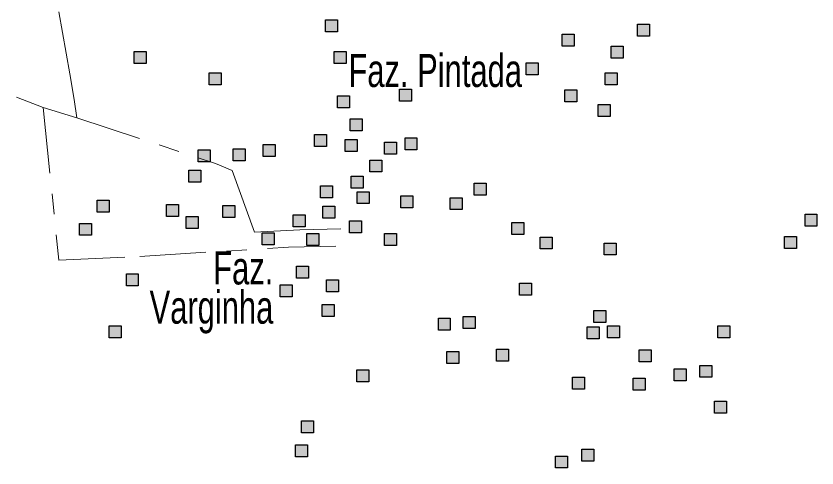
# Model space of a CAD drawing. Extents: x 445.4 to 500, y 8728.7 to 8784.
# Drawn here: x 445.43 to 449.31, y 8748.527 to 8750.716 of the extents above; entities that cross this region are included whole.
import ezdxf
from ezdxf.enums import TextEntityAlignment as Align

# ---------------------------------------------------------------- set-up
doc = ezdxf.new("R2010")
doc.units = 0
doc.header["$LTSCALE"] = 0.064
doc.linetypes.add('DOT_DASHED', pattern=[7.7, 5, -1.2, 0.3, -1.2])
doc.layers.add('2', color=7, linetype='Continuous', lineweight=25)
doc.layers.add('22', color=7, linetype='DOT_DASHED', lineweight=13)
doc.layers.add('61', color=7, linetype='Continuous')

msp = doc.modelspace()

# ---------------------------------------------------------------- hatches: boundary and pattern name
at = {"layer": '2'}
for points in [[(446.9291, 8750.6983), (446.9871, 8750.6983), (446.9871, 8750.6403), (446.9291, 8750.6403)], [(448.4407, 8750.6776), (448.4987, 8750.6776), (448.4987, 8750.6196), (448.4407, 8750.6196)], [(448.0762, 8750.6279), (448.1342, 8750.6279), (448.1342, 8750.5699), (448.0762, 8750.5699)], [(448.3123, 8750.5699), (448.3703, 8750.5699), (448.3703, 8750.5119), (448.3123, 8750.5119)], [(446.0014, 8750.545), (446.0594, 8750.545), (446.0594, 8750.487), (446.0014, 8750.487)], [(446.9705, 8750.545), (447.0285, 8750.545), (447.0285, 8750.487), (446.9705, 8750.487)], [(447.9019, 8750.49), (447.9599, 8750.49), (447.9599, 8750.432), (447.9019, 8750.432)], [(446.3659, 8750.4414), (446.4239, 8750.4414), (446.4239, 8750.3834), (446.3659, 8750.3834)], [(448.2833, 8750.4414), (448.3413, 8750.4414), (448.3413, 8750.3834), (448.2833, 8750.3834)], [(446.9871, 8750.3295), (447.0451, 8750.3295), (447.0451, 8750.2715), (446.9871, 8750.2715)], [(447.2873, 8750.3627), (447.3453, 8750.3627), (447.3453, 8750.3047), (447.2873, 8750.3047)], [(448.0886, 8750.3585), (448.1466, 8750.3585), (448.1466, 8750.3005), (448.0886, 8750.3005)], [(448.2502, 8750.2881), (448.3082, 8750.2881), (448.3082, 8750.2301), (448.2502, 8750.2301)], [(447.0492, 8750.2177), (447.1072, 8750.2177), (447.1072, 8750.1597), (447.0492, 8750.1597)], [(446.8752, 8750.1431), (446.9332, 8750.1431), (446.9332, 8750.0851), (446.8752, 8750.0851)], [(446.6268, 8750.0933), (446.6848, 8750.0933), (446.6848, 8750.0353), (446.6268, 8750.0353)], [(447.0243, 8750.1182), (447.0823, 8750.1182), (447.0823, 8750.0602), (447.0243, 8750.0602)], [(447.2148, 8750.1058), (447.2728, 8750.1058), (447.2728, 8750.0478), (447.2148, 8750.0478)], [(447.3142, 8750.1265), (447.3722, 8750.1265), (447.3722, 8750.0685), (447.3142, 8750.0685)], [(446.312, 8750.0685), (446.37, 8750.0685), (446.37, 8750.0105), (446.312, 8750.0105)], [(446.4818, 8750.0726), (446.5398, 8750.0726), (446.5398, 8750.0146), (446.4818, 8750.0146)], [(447.1444, 8750.0188), (447.2024, 8750.0188), (447.2024, 8749.9608), (447.1444, 8749.9608)], [(446.2665, 8749.969), (446.3245, 8749.969), (446.3245, 8749.911), (446.2665, 8749.911)], [(447.0533, 8749.94), (447.1113, 8749.94), (447.1113, 8749.882), (447.0533, 8749.882)], [(447.6497, 8749.9069), (447.7077, 8749.9069), (447.7077, 8749.8489), (447.6497, 8749.8489)], [(446.9042, 8749.8944), (446.9622, 8749.8944), (446.9622, 8749.8364), (446.9042, 8749.8364)], [(447.0823, 8749.8654), (447.1403, 8749.8654), (447.1403, 8749.8074), (447.0823, 8749.8074)], [(445.8233, 8749.824), (445.8813, 8749.824), (445.8813, 8749.766), (445.8233, 8749.766)], [(447.2935, 8749.8447), (447.3515, 8749.8447), (447.3515, 8749.7867), (447.2935, 8749.7867)], [(447.5337, 8749.8364), (447.5917, 8749.8364), (447.5917, 8749.7784), (447.5337, 8749.7784)], [(446.1588, 8749.8033), (446.2168, 8749.8033), (446.2168, 8749.7453), (446.1588, 8749.7453)], [(446.4321, 8749.7991), (446.4901, 8749.7991), (446.4901, 8749.7411), (446.4321, 8749.7411)], [(446.9166, 8749.795), (446.9746, 8749.795), (446.9746, 8749.737), (446.9166, 8749.737)], [(446.254, 8749.7453), (446.312, 8749.7453), (446.312, 8749.6873), (446.254, 8749.6873)], [(446.7717, 8749.7535), (446.8297, 8749.7535), (446.8297, 8749.6955), (446.7717, 8749.6955)], [(449.2521, 8749.7568), (449.3101, 8749.7568), (449.3101, 8749.6988), (449.2521, 8749.6988)], [(445.7364, 8749.7121), (445.7944, 8749.7121), (445.7944, 8749.6541), (445.7364, 8749.6541)], [(447.045, 8749.7245), (447.103, 8749.7245), (447.103, 8749.6665), (447.045, 8749.6665)], [(447.8319, 8749.7163), (447.8899, 8749.7163), (447.8899, 8749.6583), (447.8319, 8749.6583)], [(446.6226, 8749.6665), (446.6806, 8749.6665), (446.6806, 8749.6085), (446.6226, 8749.6085)], [(446.838, 8749.6624), (446.896, 8749.6624), (446.896, 8749.6044), (446.838, 8749.6044)], [(447.2148, 8749.6624), (447.2728, 8749.6624), (447.2728, 8749.6044), (447.2148, 8749.6044)], [(447.9685, 8749.6458), (448.0265, 8749.6458), (448.0265, 8749.5878), (447.9685, 8749.5878)], [(449.1527, 8749.649), (449.2107, 8749.649), (449.2107, 8749.591), (449.1527, 8749.591)], [(448.2791, 8749.6168), (448.3371, 8749.6168), (448.3371, 8749.5588), (448.2791, 8749.5588)], [(446.7883, 8749.5049), (446.8463, 8749.5049), (446.8463, 8749.4469), (446.7883, 8749.4469)], [(445.9641, 8749.4676), (446.0221, 8749.4676), (446.0221, 8749.4096), (445.9641, 8749.4096)], [(446.9332, 8749.4386), (446.9912, 8749.4386), (446.9912, 8749.3806), (446.9332, 8749.3806)], [(446.7096, 8749.4138), (446.7676, 8749.4138), (446.7676, 8749.3558), (446.7096, 8749.3558)], [(447.8692, 8749.422), (447.9272, 8749.422), (447.9272, 8749.364), (447.8692, 8749.364)], [(446.9125, 8749.3184), (446.9705, 8749.3184), (446.9705, 8749.2604), (446.9125, 8749.2604)], [(448.2294, 8749.2894), (448.2874, 8749.2894), (448.2874, 8749.2314), (448.2294, 8749.2314)], [(447.4757, 8749.2521), (447.5337, 8749.2521), (447.5337, 8749.1941), (447.4757, 8749.1941)], [(447.5958, 8749.2604), (447.6538, 8749.2604), (447.6538, 8749.2024), (447.5958, 8749.2024)], [(445.8813, 8749.2149), (445.9393, 8749.2149), (445.9393, 8749.1569), (445.8813, 8749.1569)], [(448.1963, 8749.2107), (448.2543, 8749.2107), (448.2543, 8749.1527), (448.1963, 8749.1527)], [(448.2957, 8749.2149), (448.3537, 8749.2149), (448.3537, 8749.1569), (448.2957, 8749.1569)], [(448.8299, 8749.2149), (448.8879, 8749.2149), (448.8879, 8749.1569), (448.8299, 8749.1569)], [(447.5171, 8749.0905), (447.5751, 8749.0905), (447.5751, 8749.0325), (447.5171, 8749.0325)], [(447.7573, 8749.103), (447.8153, 8749.103), (447.8153, 8749.045), (447.7573, 8749.045)], [(448.4489, 8749.0988), (448.5069, 8749.0988), (448.5069, 8749.0408), (448.4489, 8749.0408)], [(448.6187, 8749.0077), (448.6767, 8749.0077), (448.6767, 8748.9497), (448.6187, 8748.9497)], [(448.743, 8749.0242), (448.801, 8749.0242), (448.801, 8748.9662), (448.743, 8748.9662)], [(447.0803, 8749.0022), (447.1383, 8749.0022), (447.1383, 8748.9442), (447.0803, 8748.9442)], [(448.1259, 8748.9662), (448.1839, 8748.9662), (448.1839, 8748.9082), (448.1259, 8748.9082)], [(448.4199, 8748.9621), (448.4779, 8748.9621), (448.4779, 8748.9041), (448.4199, 8748.9041)], [(448.8134, 8748.8502), (448.8714, 8748.8502), (448.8714, 8748.7922), (448.8134, 8748.7922)], [(446.8131, 8748.7549), (446.8711, 8748.7549), (446.8711, 8748.6969), (446.8131, 8748.6969)], [(446.7841, 8748.6389), (446.8421, 8748.6389), (446.8421, 8748.5809), (446.7841, 8748.5809)], [(448.0431, 8748.585), (448.1011, 8748.585), (448.1011, 8748.527), (448.0431, 8748.527)], [(448.1715, 8748.6181), (448.2295, 8748.6181), (448.2295, 8748.5601), (448.1715, 8748.5601)]]:
    msp.add_hatch(color=256, dxfattribs=at).paths.add_polyline_path(points)

# ---------------------------------------------------------------- linework, layer by layer
for points in [[(446.9291, 8750.6983), (446.9871, 8750.6983), (446.9871, 8750.6403), (446.9291, 8750.6403)], [(448.4407, 8750.6776), (448.4987, 8750.6776), (448.4987, 8750.6196), (448.4407, 8750.6196)], [(448.0762, 8750.6279), (448.1342, 8750.6279), (448.1342, 8750.5699), (448.0762, 8750.5699)], [(448.3123, 8750.5699), (448.3703, 8750.5699), (448.3703, 8750.5119), (448.3123, 8750.5119)], [(446.0014, 8750.545), (446.0594, 8750.545), (446.0594, 8750.487), (446.0014, 8750.487)], [(446.9705, 8750.545), (447.0285, 8750.545), (447.0285, 8750.487), (446.9705, 8750.487)], [(447.9019, 8750.49), (447.9599, 8750.49), (447.9599, 8750.432), (447.9019, 8750.432)], [(446.3659, 8750.4414), (446.4239, 8750.4414), (446.4239, 8750.3834), (446.3659, 8750.3834)], [(448.2833, 8750.4414), (448.3413, 8750.4414), (448.3413, 8750.3834), (448.2833, 8750.3834)], [(446.9871, 8750.3295), (447.0451, 8750.3295), (447.0451, 8750.2715), (446.9871, 8750.2715)], [(447.2873, 8750.3627), (447.3453, 8750.3627), (447.3453, 8750.3047), (447.2873, 8750.3047)], [(448.0886, 8750.3585), (448.1466, 8750.3585), (448.1466, 8750.3005), (448.0886, 8750.3005)], [(448.2502, 8750.2881), (448.3082, 8750.2881), (448.3082, 8750.2301), (448.2502, 8750.2301)], [(447.0492, 8750.2177), (447.1072, 8750.2177), (447.1072, 8750.1597), (447.0492, 8750.1597)], [(446.8752, 8750.1431), (446.9332, 8750.1431), (446.9332, 8750.0851), (446.8752, 8750.0851)], [(446.6268, 8750.0933), (446.6848, 8750.0933), (446.6848, 8750.0353), (446.6268, 8750.0353)], [(447.0243, 8750.1182), (447.0823, 8750.1182), (447.0823, 8750.0602), (447.0243, 8750.0602)], [(447.2148, 8750.1058), (447.2728, 8750.1058), (447.2728, 8750.0478), (447.2148, 8750.0478)], [(447.3142, 8750.1265), (447.3722, 8750.1265), (447.3722, 8750.0685), (447.3142, 8750.0685)], [(446.312, 8750.0685), (446.37, 8750.0685), (446.37, 8750.0105), (446.312, 8750.0105)], [(446.4818, 8750.0726), (446.5398, 8750.0726), (446.5398, 8750.0146), (446.4818, 8750.0146)], [(447.1444, 8750.0188), (447.2024, 8750.0188), (447.2024, 8749.9608), (447.1444, 8749.9608)], [(446.2665, 8749.969), (446.3245, 8749.969), (446.3245, 8749.911), (446.2665, 8749.911)], [(447.0533, 8749.94), (447.1113, 8749.94), (447.1113, 8749.882), (447.0533, 8749.882)], [(447.6497, 8749.9069), (447.7077, 8749.9069), (447.7077, 8749.8489), (447.6497, 8749.8489)], [(446.9042, 8749.8944), (446.9622, 8749.8944), (446.9622, 8749.8364), (446.9042, 8749.8364)], [(447.0823, 8749.8654), (447.1403, 8749.8654), (447.1403, 8749.8074), (447.0823, 8749.8074)], [(445.8233, 8749.824), (445.8813, 8749.824), (445.8813, 8749.766), (445.8233, 8749.766)], [(447.2935, 8749.8447), (447.3515, 8749.8447), (447.3515, 8749.7867), (447.2935, 8749.7867)], [(447.5337, 8749.8364), (447.5917, 8749.8364), (447.5917, 8749.7784), (447.5337, 8749.7784)], [(446.1588, 8749.8033), (446.2168, 8749.8033), (446.2168, 8749.7453), (446.1588, 8749.7453)], [(446.4321, 8749.7991), (446.4901, 8749.7991), (446.4901, 8749.7411), (446.4321, 8749.7411)], [(446.9166, 8749.795), (446.9746, 8749.795), (446.9746, 8749.737), (446.9166, 8749.737)], [(446.254, 8749.7453), (446.312, 8749.7453), (446.312, 8749.6873), (446.254, 8749.6873)], [(446.7717, 8749.7535), (446.8297, 8749.7535), (446.8297, 8749.6955), (446.7717, 8749.6955)], [(449.2521, 8749.7568), (449.3101, 8749.7568), (449.3101, 8749.6988), (449.2521, 8749.6988)], [(445.7364, 8749.7121), (445.7944, 8749.7121), (445.7944, 8749.6541), (445.7364, 8749.6541)], [(447.045, 8749.7245), (447.103, 8749.7245), (447.103, 8749.6665), (447.045, 8749.6665)], [(447.8319, 8749.7163), (447.8899, 8749.7163), (447.8899, 8749.6583), (447.8319, 8749.6583)], [(446.6226, 8749.6665), (446.6806, 8749.6665), (446.6806, 8749.6085), (446.6226, 8749.6085)], [(446.838, 8749.6624), (446.896, 8749.6624), (446.896, 8749.6044), (446.838, 8749.6044)], [(447.2148, 8749.6624), (447.2728, 8749.6624), (447.2728, 8749.6044), (447.2148, 8749.6044)], [(447.9685, 8749.6458), (448.0265, 8749.6458), (448.0265, 8749.5878), (447.9685, 8749.5878)], [(449.1527, 8749.649), (449.2107, 8749.649), (449.2107, 8749.591), (449.1527, 8749.591)], [(448.2791, 8749.6168), (448.3371, 8749.6168), (448.3371, 8749.5588), (448.2791, 8749.5588)], [(446.7883, 8749.5049), (446.8463, 8749.5049), (446.8463, 8749.4469), (446.7883, 8749.4469)], [(445.9641, 8749.4676), (446.0221, 8749.4676), (446.0221, 8749.4096), (445.9641, 8749.4096)], [(446.9332, 8749.4386), (446.9912, 8749.4386), (446.9912, 8749.3806), (446.9332, 8749.3806)], [(446.7096, 8749.4138), (446.7676, 8749.4138), (446.7676, 8749.3558), (446.7096, 8749.3558)], [(447.8692, 8749.422), (447.9272, 8749.422), (447.9272, 8749.364), (447.8692, 8749.364)], [(446.9125, 8749.3184), (446.9705, 8749.3184), (446.9705, 8749.2604), (446.9125, 8749.2604)], [(448.2294, 8749.2894), (448.2874, 8749.2894), (448.2874, 8749.2314), (448.2294, 8749.2314)], [(447.4757, 8749.2521), (447.5337, 8749.2521), (447.5337, 8749.1941), (447.4757, 8749.1941)], [(447.5958, 8749.2604), (447.6538, 8749.2604), (447.6538, 8749.2024), (447.5958, 8749.2024)], [(445.8813, 8749.2149), (445.9393, 8749.2149), (445.9393, 8749.1569), (445.8813, 8749.1569)], [(448.1963, 8749.2107), (448.2543, 8749.2107), (448.2543, 8749.1527), (448.1963, 8749.1527)], [(448.2957, 8749.2149), (448.3537, 8749.2149), (448.3537, 8749.1569), (448.2957, 8749.1569)], [(448.8299, 8749.2149), (448.8879, 8749.2149), (448.8879, 8749.1569), (448.8299, 8749.1569)], [(447.5171, 8749.0905), (447.5751, 8749.0905), (447.5751, 8749.0325), (447.5171, 8749.0325)], [(447.7573, 8749.103), (447.8153, 8749.103), (447.8153, 8749.045), (447.7573, 8749.045)], [(448.4489, 8749.0988), (448.5069, 8749.0988), (448.5069, 8749.0408), (448.4489, 8749.0408)], [(448.6187, 8749.0077), (448.6767, 8749.0077), (448.6767, 8748.9497), (448.6187, 8748.9497)], [(448.743, 8749.0242), (448.801, 8749.0242), (448.801, 8748.9662), (448.743, 8748.9662)], [(447.0803, 8749.0022), (447.1383, 8749.0022), (447.1383, 8748.9442), (447.0803, 8748.9442)], [(448.1259, 8748.9662), (448.1839, 8748.9662), (448.1839, 8748.9082), (448.1259, 8748.9082)], [(448.4199, 8748.9621), (448.4779, 8748.9621), (448.4779, 8748.9041), (448.4199, 8748.9041)], [(448.8134, 8748.8502), (448.8714, 8748.8502), (448.8714, 8748.7922), (448.8134, 8748.7922)], [(446.8131, 8748.7549), (446.8711, 8748.7549), (446.8711, 8748.6969), (446.8131, 8748.6969)], [(446.7841, 8748.6389), (446.8421, 8748.6389), (446.8421, 8748.5809), (446.7841, 8748.5809)], [(448.0431, 8748.585), (448.1011, 8748.585), (448.1011, 8748.527), (448.0431, 8748.527)], [(448.1715, 8748.6181), (448.2295, 8748.6181), (448.2295, 8748.5601), (448.1715, 8748.5601)]]:
    msp.add_lwpolyline(points, close=True, dxfattribs=at)
at = {"layer": '22'}
for points in [[(445.4295, 8751.7489), (445.4572, 8751.6937), (445.4869, 8751.5759), (445.5307, 8751.3482), (445.6902, 8750.4356), (445.712, 8750.3115), (445.7243, 8750.224)], [(445.4324, 8750.3239), (445.5617, 8750.2731), (445.7243, 8750.224)], [(445.5617, 8750.2731), (445.6368, 8749.5344), (446.0294, 8749.5518), (446.7496, 8749.5966), (446.9787, 8749.6016)], [(445.7243, 8750.224), (446.3952, 8750.0013), (446.4775, 8749.9678), (446.5857, 8749.6698), (446.8048, 8749.6812), (447.003, 8749.685)]]:
    msp.add_lwpolyline(points, dxfattribs=at)

# ---------------------------------------------------------------- texts
at = {"layer": '61', "width": 0.7}
msp.add_text('Faz. Pintada', height=0.16, dxfattribs=at).set_placement((447.04, 8750.3727))
for s, p in [('       Faz.', (446.6761, 8749.4162)), ('Varginha', (446.6761, 8749.2262))]:
    msp.add_text(s, height=0.16, dxfattribs=at).set_placement(p, align=Align.RIGHT)

doc.saveas('drawing.dxf')
